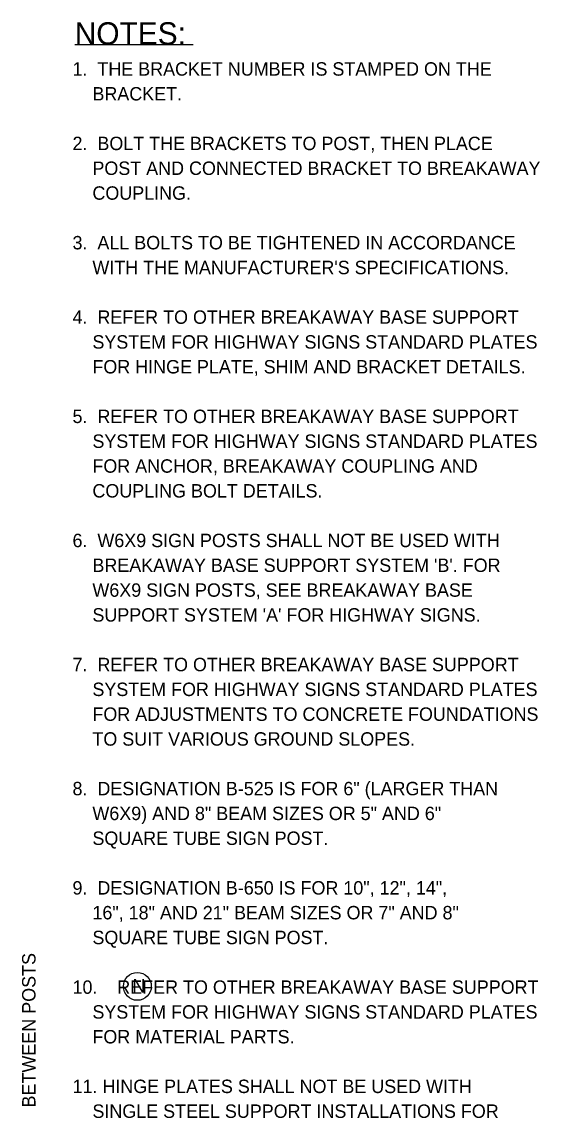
# Model space of a CAD drawing. Extents: x 12.3 to 19.6, y 18.8 to 29.6.
# Drawn here: x 16.521 to 18.841, y 24.68 to 29.583 of the extents above; entities that cross this region are included whole.
import ezdxf

# ---------------------------------------------------------------- set-up
doc = ezdxf.new("R2010")
doc.units = 0
doc.layers.add('BORD-LINE', color=7, linetype='Continuous')

msp = doc.modelspace()

# ---------------------------------------------------------------- linework, layer by layer
at = {"layer": 'BORD-LINE'}
msp.add_line((16.7575, 29.4815), (17.2879, 29.4815), dxfattribs=at)
msp.add_circle((17.038, 25.2689), 0.0623, dxfattribs=at)

# ---------------------------------------------------------------- texts
for s, height, p in [('NOTES:', 0.1, (16.7575, 29.4815)), ('1.  THE BRACKET NUMBER IS STAMPED ON THE', 0.06, (16.7475, 29.3426)), ('    BRACKET.', 0.06, (16.7475, 29.2316)), ('2.  BOLT THE BRACKETS TO POST, THEN PLACE ', 0.06, (16.7475, 29.0096)), ('    POST AND CONNECTED BRACKET TO BREAKAWAY', 0.06, (16.7475, 28.8986)), ('    COUPLING.', 0.06, (16.7475, 28.7876)), ('3.  ALL BOLTS TO BE TIGHTENED IN ACCORDANCE ', 0.06, (16.7475, 28.5656)), ("    WITH THE MANUFACTURER'S SPECIFICATIONS.", 0.06, (16.7475, 28.4546)), ('4.  REFER TO OTHER BREAKAWAY BASE SUPPORT', 0.06, (16.7475, 28.2326)), ('    SYSTEM FOR HIGHWAY SIGNS STANDARD PLATES', 0.06, (16.7475, 28.1216)), ('    FOR HINGE PLATE, SHIM AND BRACKET DETAILS.', 0.06, (16.7475, 28.0106)), ('5.  REFER TO OTHER BREAKAWAY BASE SUPPORT ', 0.06, (16.7475, 27.7886)), ('    SYSTEM FOR HIGHWAY SIGNS STANDARD PLATES', 0.06, (16.7475, 27.6776)), ('    FOR ANCHOR, BREAKAWAY COUPLING AND ', 0.06, (16.7475, 27.5666)), ('    COUPLING BOLT DETAILS.', 0.06, (16.7475, 27.4556)), ('6.  W6X9 SIGN POSTS SHALL NOT BE USED WITH', 0.06, (16.7475, 27.2336)), ("    BREAKAWAY BASE SUPPORT SYSTEM 'B'. FOR", 0.06, (16.7475, 27.1226)), ('    W6X9 SIGN POSTS, SEE BREAKAWAY BASE', 0.06, (16.7475, 27.0116)), ("    SUPPORT SYSTEM 'A' FOR HIGHWAY SIGNS.", 0.06, (16.7475, 26.9006)), ('7.  REFER TO OTHER BREAKAWAY BASE SUPPORT', 0.06, (16.7475, 26.6786)), ('    SYSTEM FOR HIGHWAY SIGNS STANDARD PLATES', 0.06, (16.7475, 26.5676)), ('    FOR ADJUSTMENTS TO CONCRETE FOUNDATIONS', 0.06, (16.7475, 26.4566)), ('    TO SUIT VARIOUS GROUND SLOPES.', 0.06, (16.7475, 26.3456)), ('8.  DESIGNATION B-525 IS FOR 6" (LARGER THAN', 0.06, (16.7475, 26.1236)), ('    W6X9) AND 8" BEAM SIZES OR 5" AND 6" ', 0.06, (16.7475, 26.0126)), ('    SQUARE TUBE SIGN POST.', 0.06, (16.7475, 25.9016)), ('9.  DESIGNATION B-650 IS FOR 10", 12", 14", ', 0.06, (16.7475, 25.6796)), ('    16", 18" AND 21" BEAM SIZES OR 7" AND 8" ', 0.06, (16.7475, 25.5686)), ('    SQUARE TUBE SIGN POST.', 0.06, (16.7475, 25.4576)), ('N', 0.06, (17.0157, 25.2414)), ('10.    REFER TO OTHER BREAKAWAY BASE SUPPORT ', 0.06, (16.7475, 25.2356)), ('    SYSTEM FOR HIGHWAY SIGNS STANDARD PLATES', 0.06, (16.7475, 25.1246)), ('    FOR MATERIAL PARTS.', 0.06, (16.7475, 25.0136)), ('11. HINGE PLATES SHALL NOT BE USED WITH ', 0.06, (16.7475, 24.7916)), ('    SINGLE STEEL SUPPORT INSTALLATIONS FOR ', 0.06, (16.7475, 24.6806))]:
    msp.add_text(s, height=height, dxfattribs=at).set_placement(p)
msp.add_text('BETWEEN POSTS', height=0.06, rotation=90, dxfattribs=at).set_placement((16.5818, 24.7272))

doc.saveas('drawing.dxf')
